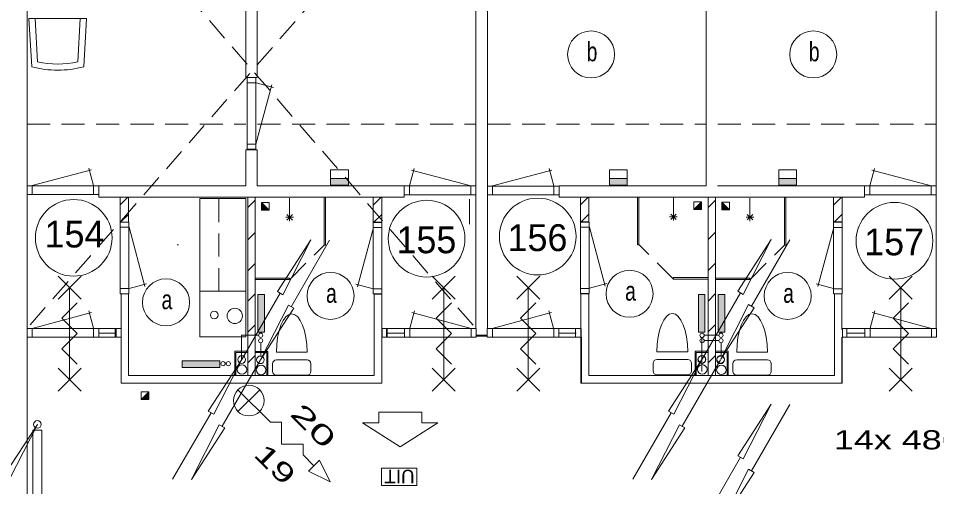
# Model space of a CAD drawing. Extents: x 295824 to 414724, y 24924 to 109024.
# Drawn here: x 301977 to 313944, y 70117 to 76222 of the extents above; entities that cross this region are included whole.
import ezdxf
from ezdxf.enums import TextEntityAlignment as Align

# ---------------------------------------------------------------- set-up
doc = ezdxf.new("R2010")
doc.units = 0
doc.header["$LTSCALE"] = 100
doc.linetypes.add('LONG_DASHED', pattern=[7.5, 6, -1.5])
doc.linetypes.add('MEDIUM_DASHED', pattern=[4.5, 3, -1.5])
doc.layers.add('16', color=7, linetype='Continuous', lineweight=13)
doc.layers.add('61', color=7, linetype='Continuous', lineweight=13)

msp = doc.modelspace()

# ---------------------------------------------------------------- hatches: boundary and pattern name
at = {"layer": '16'}
for points in [[(306277.8, 74047.1), (306046.2, 74047.1), (306046.2, 74133.6), (306277.8, 74133.6)], [(309911.3, 74047.1), (309679.8, 74047.1), (309679.8, 74133.6), (309911.3, 74133.6)], [(312117.3, 74047.1), (311885.8, 74047.1), (311885.8, 74133.6), (312117.3, 74133.6)], [(305098.5, 72622), (305183.9, 72622), (305183.9, 72129.8), (305098.5, 72129.8)], [(310838.6, 72622), (310924, 72622), (310924, 72129.8), (310838.6, 72129.8)], [(311097.8, 72622), (311183.2, 72622), (311183.2, 72129.8), (311097.8, 72129.8)], [(304110.9, 71671.9), (304110.9, 71757.4), (304603.1, 71757.4), (304603.1, 71671.9)]]:
    msp.add_hatch(color=256, dxfattribs=at).paths.add_polyline_path(points)
at = {"layer": '61'}
for points in [[(305244.4, 73722.8), (305144.4, 73822.8), (305144.4, 73722.8)], [(310781.4, 73729.4), (310881.4, 73829.4), (310881.4, 73729.4)], [(311243.8, 73724.1), (311143.8, 73824.1), (311143.8, 73724.1)], [(303578.3, 71252.8), (303678.3, 71352.8), (303678.3, 71252.8)]]:
    msp.add_hatch(color=256, dxfattribs=at).paths.add_polyline_path(points)

# ---------------------------------------------------------------- linework, layer by layer
at = {"layer": '16'}
for p, q in [((306046.2, 74133.6), (306046.2, 74247.5)), ((309679.8, 74133.6), (309679.8, 74247.5)), ((311885.8, 74133.6), (311885.8, 74247.5)), ((306031, 73329.2), (305531, 72463.2)), ((312030.4, 73336.8), (311530.4, 72470.8)), ((310887.4, 71778.5), (311387.4, 72644.5)), ((304888, 71774.7), (305388, 72640.7)), ((304886.5, 71769.9), (304886.5, 72091)), ((305106.8, 72091), (304886.5, 72091)), ((310885.9, 71619.1), (310885.9, 72055.6)), ((311106.2, 72091), (310914.5, 72091)), ((305131.1, 71769.9), (304631.1, 70903.9)), ((311127.8, 71769.9), (310627.8, 70903.9)), ((312030.4, 71187.6), (311530.4, 70321.6)), ((303987.2, 70215), (304487.2, 71081)), ((309983.9, 70215), (310483.9, 71081)), ((310887.4, 69633.3), (311387.4, 70499.3))]:
    msp.add_line(p, q, dxfattribs=at)
at = {"layer": '16', "linetype": 'LONG_DASHED'}
for p, q in [((305137.7, 71830.9), (305137.7, 71994.5)), ((310914.6, 72020.2), (311106.1, 72020.2)), ((311137.1, 71830.9), (311137.1, 71994.5))]:
    msp.add_line(p, q, dxfattribs=at)
at = {"layer": '16'}
for points in [[(306277.8, 74133.6), (306277.8, 74247.5), (306046.2, 74247.5)], [(309911.3, 74133.6), (309911.3, 74247.5), (309679.8, 74247.5)], [(312117.3, 74133.6), (312117.3, 74247.5), (311885.8, 74247.5)]]:
    msp.add_lwpolyline(points, dxfattribs=at)
for points in [[(306277.8, 74047.1), (306046.2, 74047.1), (306046.2, 74133.6), (306277.8, 74133.6)], [(309911.3, 74047.1), (309679.8, 74047.1), (309679.8, 74133.6), (309911.3, 74133.6)], [(312117.3, 74047.1), (311885.8, 74047.1), (311885.8, 74133.6), (312117.3, 74133.6)], [(305788, 73333.7), (305424, 72619.7), (305352, 72661.7)], [(311787.4, 73337.5), (311423.4, 72623.5), (311351.4, 72665.5)], [(305098.5, 72622), (305183.9, 72622), (305183.9, 72129.8), (305098.5, 72129.8)], [(310838.6, 72622), (310924, 72622), (310924, 72129.8), (310838.6, 72129.8)], [(311097.8, 72622), (311183.2, 72622), (311183.2, 72129.8), (311097.8, 72129.8)], [(305131, 71770.2), (305495, 72484.2), (305567, 72442.2)], [(311130.4, 71777.8), (311494.4, 72491.8), (311566.4, 72449.8)], [(304110.9, 71671.9), (304110.9, 71757.4), (304603.1, 71757.4), (304603.1, 71671.9)], [(304887.2, 71774), (304523.2, 71060), (304451.2, 71102)], [(310883.9, 71774), (310519.9, 71060), (310447.9, 71102)], [(311787.4, 71192.3), (311423.4, 70478.3), (311351.4, 70520.3)], [(302224.6, 70928.2), (301860.6, 70214.2), (301788.6, 70256.2)], [(302281.5, 70853.7), (302281.5, 69634.3), (302163.6, 69634.3), (302163.6, 70853.7)], [(304231.1, 70210.9), (304595.1, 70924.9), (304667.1, 70882.9)], [(310227.8, 70210.9), (310591.8, 70924.9), (310663.8, 70882.9)], [(311130.4, 69628.6), (311494.4, 70342.6), (311566.4, 70300.6)]]:
    msp.add_lwpolyline(points, close=True, dxfattribs=at)
for centre, radius in [((305134.7, 72091), 27.9), ((305134.7, 72020.2), 27.9), ((310886.7, 72088), 27.9), ((310886.7, 72020.2), 27.9), ((311134.1, 72091), 27.9), ((311134.1, 72020.2), 27.9), ((304887.2, 71773.7), 50), ((304888, 71774.4), 50), ((305131, 71770.5), 50), ((305131.1, 71770.2), 50), ((310883.9, 71773.7), 50), ((310887.4, 71778.2), 50), ((311127.8, 71770.2), 50), ((311130.4, 71778.1), 50), ((304644.9, 71720), 27.9), ((304712.7, 71720), 27.9), ((302224.6, 70927.9), 50)]:
    msp.add_circle(centre, radius, dxfattribs=at)
at = {"layer": '61'}
for p, q in [((302090.1, 72179.9), (302090.1, 78890.8)), ((307940.1, 72179.6), (307940.1, 78890.8)), ((308090.1, 72179.8), (308090.1, 78890.8)), ((313940.1, 72179.8), (313940.1, 78890.8)), ((304940.1, 76611.3), (304940.1, 75450.1)), ((305090.1, 76626), (305090.1, 75450.1)), ((302227, 75655.3), (302193.6, 76221.1)), ((302783.3, 76221.1), (302751.8, 75655.2)), ((302863.4, 76221.1), (302828.4, 75591.8)), ((305090.1, 75450.1), (304940.1, 75450.1)), ((304959, 75449.3), (305073, 75449.3)), ((304959, 75382.3), (305073, 75382.3)), ((305073.6, 74581.5), (305280.6, 75354.2)), ((305074.2, 75379.9), (305301.1, 75319.2)), ((304959, 74582.3), (305073, 74582.3)), ((304940.1, 74510.2), (305090.1, 74510.2)), ((304940.1, 74510.2), (304940.1, 74040.8)), ((305090.1, 74510.2), (305090.1, 74040.8)), ((302156.8, 74041.6), (302929.6, 74248.6)), ((302955.2, 74042.2), (302894.5, 74269)), ((307075, 74038.5), (307135.8, 74265.4)), ((307873.4, 74037.9), (307100.7, 74244.9)), ((308156.5, 74036.8), (308929.3, 74243.8)), ((308955, 74037.4), (308894.2, 74264.3)), ((313075.3, 74038.5), (313136.1, 74265.4)), ((313873.7, 74037.9), (313101, 74244.9)), ((302157.6, 73926.9), (302157.6, 74040.9)), ((302957.6, 73926.9), (302957.6, 74040.9)), ((303024.6, 73926.9), (303024.6, 74040.9)), ((304940.1, 74040.8), (303025.4, 74040.8)), ((303025.4, 74040.8), (303025.4, 73890.8)), ((305090.1, 74040.8), (307004.9, 74040.8)), ((307004.9, 74040.8), (307004.9, 73890.8)), ((307005.7, 73923.2), (307005.7, 74037.2)), ((307072.7, 73923.2), (307072.7, 74037.2)), ((307872.7, 73923.2), (307872.7, 74037.2)), ((308157.3, 73922.2), (308157.3, 74036.2)), ((308957.3, 73922.2), (308957.3, 74036.2)), ((309024.3, 73922.2), (309024.3, 74036.2)), ((311090.1, 74040.8), (313005.2, 74040.8)), ((313005.2, 74040.8), (313005.2, 73890.8)), ((313006, 73923.2), (313006, 74037.2)), ((313073, 73923.2), (313073, 74037.2)), ((313873, 73923.2), (313873, 74037.2)), ((303025.4, 73890.8), (303315.1, 73890.8)), ((307004.9, 73890.8), (303025.4, 73890.8)), ((303301.8, 73789.9), (303401.5, 73889.6)), ((303303.2, 73566.1), (303303.2, 73890.2)), ((303303.2, 73890.2), (303413.2, 73890.2)), ((303413.2, 73566.1), (303413.2, 73890.2)), ((304941.8, 72071.6), (304941.8, 73872.2)), ((304966.4, 73890.8), (304966.4, 71565.8)), ((304966.9, 73754.6), (305062.7, 73850.4)), ((305062.7, 73890.8), (305062.7, 71565.8)), ((305512, 73678.6), (305512, 73878.6)), ((305961.9, 73885.1), (305961.9, 73264.6)), ((306602.2, 73566.1), (306602.2, 73890.2)), ((306602.2, 73890.2), (306712.2, 73890.2)), ((306603.9, 73789.9), (306703.6, 73889.6)), ((306605.9, 73892.1), (306719.9, 73892.1)), ((306712.2, 73566.1), (306712.2, 73890.2)), ((307854.9, 73539.4), (307854.9, 73863.5)), ((309301.2, 73791.1), (309400.9, 73890.8)), ((309302.7, 73567.3), (309302.7, 73891.4)), ((309302.7, 73891.4), (309412.6, 73891.4)), ((309412.6, 73567.3), (309412.6, 73891.4)), ((310063.9, 73891.7), (310063.9, 73271.2)), ((310513.7, 73685.2), (310513.7, 73885.2)), ((310965.8, 73892), (310965.8, 71567)), ((310966.3, 73755.8), (311062.1, 73851.6)), ((311062.1, 73892), (311062.1, 71567)), ((311511.5, 73679.9), (311511.5, 73879.9)), ((311961.3, 73886.4), (311961.3, 73265.9)), ((312601.6, 73567.3), (312601.6, 73891.4)), ((312601.6, 73891.4), (312711.6, 73891.4)), ((312603.3, 73791.1), (312703, 73890.8)), ((312711.6, 73567.3), (312711.6, 73891.4)), ((303314.1, 73567.3), (303413.8, 73667)), ((305462, 73628.6), (305562, 73628.6)), ((305476.7, 73664), (305547.4, 73593.3)), ((305476.7, 73593.3), (305547.4, 73664)), ((305512, 73678.6), (305512, 73578.6)), ((306612.5, 73567.3), (306712.2, 73667)), ((309313.5, 73568.5), (309413.2, 73668.2)), ((310563.7, 73635.2), (310463.7, 73635.2)), ((310549.1, 73670.6), (310478.4, 73599.9)), ((310549.1, 73599.9), (310478.4, 73670.6)), ((310513.7, 73685.2), (310513.7, 73585.2)), ((311461.5, 73629.9), (311561.5, 73629.9)), ((311476.1, 73665.2), (311546.8, 73594.5)), ((311476.1, 73594.5), (311546.8, 73665.2)), ((311511.5, 73679.9), (311511.5, 73579.9)), ((312611.9, 73568.5), (312711.6, 73668.2)), ((303301.5, 73499.8), (303415.5, 73499.8)), ((303303.2, 73566.1), (303413.2, 73566.1)), ((303418.6, 73500.6), (303625.7, 72727.8)), ((306602.9, 73496.3), (306395.8, 72723.6)), ((306714.9, 73495.6), (306600.9, 73495.6)), ((306601.5, 73562.6), (306715.5, 73562.6)), ((306602.2, 73566.1), (306712.2, 73566.1)), ((306714.9, 73562.6), (306714.9, 72628.6)), ((309300.9, 73566.5), (309300.9, 72634)), ((309300.9, 73501), (309414.9, 73501)), ((309302.7, 73567.3), (309412.6, 73567.3)), ((309418, 73501.8), (309625.1, 72729.1)), ((312602.3, 73497.6), (312395.2, 72724.8)), ((312714.3, 73496.8), (312600.3, 73496.8)), ((312600.9, 73563.8), (312714.9, 73563.8)), ((312601.6, 73567.3), (312711.6, 73567.3)), ((312714.3, 73563.8), (312714.3, 72629.8)), ((304966.9, 73336.5), (305062.7, 73432.3)), ((310966.3, 73337.7), (311062.1, 73433.5)), ((304046.5, 73270), (304064.5, 73270)), ((304966.9, 72931.9), (305062.7, 73027.7)), ((310966.3, 72933.1), (311062.1, 73028.9)), ((306715.1, 72958.1), (306715.1, 72065.8)), ((302794.8, 72863), (302494.8, 72563)), ((302494.8, 72863), (302794.8, 72563)), ((305061.5, 72817.1), (305511, 72817.1)), ((305061.9, 72835.1), (305511, 72835.1)), ((305511, 72817.1), (305511, 72835.1)), ((307670.3, 72863), (307370.3, 72563)), ((307370.3, 72863), (307670.3, 72563)), ((308771.2, 72863), (308471.2, 72563)), ((308471.2, 72863), (308771.2, 72563)), ((309418.7, 72703.4), (309645.5, 72764.2)), ((310963.9, 72841.7), (310514.8, 72841.7)), ((310514.8, 72823.7), (310514.8, 72841.7)), ((310964.2, 72823.7), (310514.8, 72823.7)), ((311060.9, 72818.4), (311510.4, 72818.4)), ((311061.3, 72836.4), (311510.4, 72836.4)), ((311510.4, 72818.4), (311510.4, 72836.4)), ((313627, 72863), (313327, 72563)), ((313327, 72863), (313627, 72563)), ((302644.8, 71513), (302644.8, 72713)), ((303301.5, 72699.8), (303415.5, 72699.8)), ((303419.3, 72702.2), (303646.1, 72762.9)), ((304342, 72666.3), (304939.4, 72666.3)), ((306602.2, 72697.9), (306375.4, 72758.7)), ((306714.9, 72695.6), (306600.9, 72695.6)), ((307520.3, 71513), (307520.3, 72713)), ((308621.2, 71513), (308621.2, 72713)), ((309300.9, 72701), (309414.9, 72701)), ((312601.6, 72699.1), (312374.8, 72759.9)), ((312714.3, 72696.8), (312600.3, 72696.8)), ((313477, 71513), (313477, 72713)), ((303307.4, 72629.2), (303412.7, 72629.2)), ((303315.1, 72631.2), (303315.1, 72180.6)), ((304966.9, 72535.9), (305062.7, 72631.7)), ((306612.7, 72627.8), (306612.7, 71565.8)), ((306612.7, 72627.8), (306707.4, 72627.8)), ((309306.8, 72630.4), (309306.8, 72064.6)), ((309306.8, 72630.4), (309412.1, 72630.4)), ((310966.3, 72537.2), (311062.1, 72632.9)), ((312612.1, 72629), (312612.1, 71567)), ((312612.1, 72629), (312706.8, 72629)), ((312706.8, 72629), (312706.8, 72167)), ((302953.9, 72181), (302893.2, 72407.9)), ((307078.8, 72181.1), (307139.5, 72407.9)), ((308951.6, 72181), (308890.8, 72407.9)), ((313078.9, 72181.1), (313139.7, 72407.9)), ((302155.5, 72180.4), (302928.2, 72387.5)), ((307877.2, 72180.4), (307104.4, 72387.5)), ((308153.2, 72180.4), (308925.9, 72387.5)), ((313877.3, 72180.4), (313104.6, 72387.5)), ((302156.3, 72065.8), (302156.3, 72179.8)), ((302956.3, 72065.8), (302956.3, 72179.8)), ((303023.3, 72065.8), (303023.3, 72179.8)), ((303239.2, 72065.8), (303239.2, 72179.8)), ((303249.3, 72065.8), (303249.3, 72179.8)), ((304966.9, 72132.6), (305062.7, 72228.3)), ((306775.9, 72065.8), (306775.9, 72179.8)), ((306783.4, 72065.8), (306783.4, 72179.8)), ((307009.4, 72065.8), (307009.4, 72179.8)), ((307076.4, 72065.8), (307076.4, 72179.8)), ((307876.4, 72065.8), (307876.4, 72179.8)), ((308153.9, 72065.8), (308153.9, 72179.8)), ((308953.9, 72065.8), (308953.9, 72179.8)), ((309020.9, 72065.8), (309020.9, 72179.8)), ((309238.6, 72067), (309238.6, 72181)), ((310966.3, 72133.8), (311062.1, 72229.6)), ((312775.3, 72067), (312775.3, 72181)), ((313009.6, 72065.8), (313009.6, 72179.8)), ((313076.6, 72065.8), (313076.6, 72179.8)), ((313876.6, 72065.8), (313876.6, 72179.8)), ((302090.1, 69301.2), (302090.1, 72065.2)), ((303249.3, 72119.9), (303023.3, 72119.9)), ((304341.8, 72071.6), (304941.8, 72071.6)), ((306783.4, 72119.9), (307009.4, 72119.9)), ((307944.7, 72092.1), (308085.9, 72092.1)), ((307944.7, 72077.1), (308085.9, 72077.1)), ((309246.9, 72119.9), (309020.9, 72119.9)), ((312783.6, 72119.9), (313009.6, 72119.9)), ((304812.6, 71866.2), (304962.6, 71866.2)), ((304812.6, 71566.2), (304812.6, 71866.2)), ((304966.9, 71731.7), (305062.7, 71827.4)), ((305062.7, 71865.8), (305212.7, 71865.8)), ((305212.7, 71865.8), (305212.7, 71565.8)), ((305739.5, 71868.7), (305339.5, 71868.7)), ((310699.5, 71874.9), (310299.5, 71874.9)), ((310812, 71867.4), (310962, 71867.4)), ((310812, 71567.4), (310812, 71867.4)), ((310966.3, 71732.9), (311062.1, 71828.7)), ((311062.1, 71867), (311212.1, 71867)), ((311212.1, 71867), (311212.1, 71567)), ((311738.9, 71869.9), (311338.9, 71869.9)), ((305289.5, 71618.7), (305289.5, 71718.7)), ((305339.5, 71768.7), (305739.5, 71768.7)), ((305789.5, 71718.7), (305789.5, 71618.7)), ((310249.5, 71624.9), (310249.5, 71724.9)), ((310299.5, 71774.9), (310699.5, 71774.9)), ((310749.5, 71724.9), (310749.5, 71624.9)), ((311288.9, 71619.9), (311288.9, 71719.9)), ((311338.9, 71769.9), (311738.9, 71769.9)), ((311788.9, 71719.9), (311788.9, 71619.9)), ((302794.8, 71663), (302494.8, 71363)), ((302494.8, 71663), (302794.8, 71363)), ((305739.5, 71568.7), (305339.5, 71568.7)), ((307670.3, 71663), (307370.3, 71363)), ((307370.3, 71663), (307670.3, 71363)), ((308771.2, 71663), (308471.2, 71363)), ((308471.2, 71663), (308771.2, 71363)), ((310699.5, 71574.9), (310299.5, 71574.9)), ((311738.9, 71569.9), (311338.9, 71569.9)), ((313627, 71663), (313327, 71363)), ((313327, 71663), (313627, 71363)), ((305121.4, 71379.7), (304838.6, 71096.9))]:
    msp.add_line(p, q, dxfattribs=at)
at = {"layer": '61', "linetype": 'MEDIUM_DASHED'}
for p, q in [((302112.4, 78915.1), (307930.8, 72187.9)), ((307950.5, 78895.5), (302112.4, 72207.6)), ((302090.1, 74844.1), (304939.8, 74844.1)), ((305093, 74844.1), (307940.7, 74844.1)), ((308091.8, 74844.1), (310940.1, 74844.1)), ((311090.6, 74844.1), (313940.8, 74844.1)), ((304588.3, 72666.3), (304588.3, 73873.6)), ((305513.1, 72817.6), (305960, 73264.5)), ((310512.7, 72824.1), (310065.8, 73271)), ((311512.5, 72818.8), (311959.4, 73265.7))]:
    msp.add_line(p, q, dxfattribs=at)
at = {"layer": '61'}
for points in [[(310940.1, 79104.8), (310940.1, 74040.8), (309025.1, 74040.8), (309025.1, 73890.8), (313005.2, 73890.8)], [(302150.7, 75591.9), (302113.4, 76221.1), (302863.4, 76221.1)], [(304959, 74515.3), (305073, 74515.3), (305073, 75449.3)], [(304959, 75449.3), (304959, 74515.3), (305073, 74515.3)], [(302090.6, 73926.9), (302090.6, 74040.9), (303024.6, 74040.9)], [(303024.6, 73926.9), (302090.6, 73926.9), (302090.6, 74040.9)], [(307939.7, 73923.2), (307939.7, 74037.2), (307005.7, 74037.2)], [(307005.7, 73923.2), (307939.7, 73923.2), (307939.7, 74037.2)], [(308090.3, 73922.2), (308090.3, 74036.2), (309024.3, 74036.2)], [(309024.3, 73922.2), (308090.3, 73922.2), (308090.3, 74036.2)], [(313940, 73923.2), (313940, 74037.2), (313006, 74037.2)], [(313006, 73923.2), (313940, 73923.2), (313940, 74037.2)], [(304341.8, 72071.6), (304341.8, 73872.2), (304941.8, 73872.2)], [(305979.9, 73885.1), (305979.9, 73264.6), (305961.9, 73264.6)], [(310045.9, 73891.7), (310045.9, 73271.2), (310063.9, 73271.2)], [(311979.3, 73886.4), (311979.3, 73265.9), (311961.3, 73265.9)], [(305144.4, 73822.8), (305144.4, 73722.8), (305244.4, 73722.8)], [(310881.4, 73829.4), (310881.4, 73729.4), (310781.4, 73729.4)], [(311143.8, 73824.1), (311143.8, 73724.1), (311243.8, 73724.1)], [(303412.7, 72629.2), (303412.7, 71565.8), (306612.7, 71565.8)], [(309412.1, 72630.4), (309412.1, 71567), (312612.1, 71567)], [(302744.8, 71713), (302544.8, 71913), (302744.8, 72113), (302544.8, 72313), (302744.8, 72513)], [(307620.3, 71713), (307420.3, 71913), (307620.3, 72113), (307420.3, 72313), (307620.3, 72513)], [(308721.2, 71713), (308521.2, 71913), (308721.2, 72113), (308521.2, 72313), (308721.2, 72513)], [(313577, 71713), (313377, 71913), (313577, 72113), (313377, 72313), (313577, 72513)], [(303315.1, 72065.2), (303315.1, 71465.8), (306715.1, 71465.8), (306715.1, 72065.8)], [(309306.8, 72067), (309306.8, 71467), (312706.8, 71467), (312706.8, 72067)], [(309315.1, 72065.8), (309315.1, 71465.8), (312715.1, 71465.8), (312715.1, 72065.8)], [(304797.6, 71566.2), (304797.6, 71881.2), (304962.6, 71881.2)], [(305062.7, 71880.8), (305227.7, 71880.8), (305227.7, 71565.8)], [(310797, 71567.4), (310797, 71882.4), (310962, 71882.4)], [(311062.1, 71882), (311227.1, 71882), (311227.1, 71567)], [(303678.3, 71352.8), (303678.3, 71252.8), (303578.3, 71252.8)], [(304838.6, 71379.7), (305262.9, 70955.5), (305404.3, 70955.5), (305404.3, 70672.6), (305687.1, 70672.6), (305687.1, 70531.2), (305828.5, 70389.8)]]:
    msp.add_lwpolyline(points, dxfattribs=at)
for points in [[(305144.4, 73822.8), (305244.4, 73822.8), (305244.4, 73722.8)], [(305244.4, 73722.8), (305144.4, 73822.8), (305144.4, 73722.8)], [(310881.4, 73829.4), (310781.4, 73829.4), (310781.4, 73729.4)], [(310781.4, 73729.4), (310881.4, 73829.4), (310881.4, 73729.4)], [(311143.8, 73824.1), (311243.8, 73824.1), (311243.8, 73724.1)], [(311243.8, 73724.1), (311143.8, 73824.1), (311143.8, 73724.1)], [(303301.5, 72631.9), (303415.5, 72631.9), (303415.5, 73565.9), (303301.5, 73565.9)], [(306714.9, 73562.6), (306714.9, 72628.6), (306600.9, 72628.6), (306600.9, 73562.6)], [(309300.9, 72633.1), (309414.9, 72633.1), (309414.9, 73567.1), (309300.9, 73567.1)], [(312714.3, 73563.8), (312714.3, 72629.8), (312600.3, 72629.8), (312600.3, 73563.8)], [(302089.3, 72065.8), (302089.3, 72179.8), (303315.7, 72179.8), (303315.7, 72065.8)], [(302089.3, 72065.8), (302089.3, 72179.8), (303315.7, 72179.8), (303315.7, 72065.8)], [(306716.4, 72065.8), (306716.4, 72179.8), (307943.4, 72179.8), (307943.4, 72065.8)], [(308086.9, 72065.8), (308086.9, 72179.8), (309313.3, 72179.8), (309313.3, 72065.8)], [(308086.9, 72065.8), (308086.9, 72179.8), (309313.3, 72179.8), (309313.3, 72065.8)], [(312716.6, 72065.8), (312716.6, 72179.8), (313943.6, 72179.8), (313943.6, 72065.8)], [(303678.3, 71352.8), (303578.3, 71352.8), (303578.3, 71252.8)], [(303578.3, 71252.8), (303678.3, 71352.8), (303678.3, 71252.8)], [(306673.7, 71089.3), (307233.7, 71089.3), (307233.7, 70949.3), (307443.7, 70949.3), (306953.7, 70634.3), (306463.7, 70949.3), (306673.7, 70949.3)], [(305757.8, 70319.1), (305899.3, 70460.5), (306040.7, 70177.6)], [(307168, 70358.2), (306708.4, 70358.2), (306708.4, 70133.6), (307168, 70133.6)]]:
    msp.add_lwpolyline(points, close=True, dxfattribs=at)
for centre, radius in [((309441.3, 75751.7), 306.3), ((312336.8, 75751.7), 306.3), ((302697.7, 73360.8), 500), ((307297.3, 73350.1), 500), ((308745.1, 73377.9), 500), ((313394.5, 73322.2), 500), ((306044.7, 72603.3), 306.3), ((309942.5, 72631.2), 306.3), ((312002.7, 72603.3), 306.3), ((303900.9, 72519.7), 306.3), ((304528.9, 72355.1), 50), ((304796.8, 72342.8), 100), ((304890.2, 71643.7), 62.5), ((305140.2, 71638.2), 62.5), ((310889.6, 71644.9), 62.5), ((311139.5, 71639.4), 62.5), ((304980, 71238.3), 200)]:
    msp.add_circle(centre, radius, dxfattribs=at)
for centre, radius, start, end in [((302489.6, 76831.5), 1205.2, 257.41626, 282.56606), ((302489.6, 76831.5), 1285.2, 254.70731, 285.28507), ((305339.5, 71718.7), 50, 90, 180), ((305739.5, 71718.7), 50, 0, 90), ((310299.5, 71724.9), 50, 90, 180), ((310699.5, 71724.9), 50, 0, 90), ((311338.9, 71720), 50, 90, 180), ((311738.9, 71720), 50, 0, 90), ((305339.5, 71618.7), 50, 180, 270), ((305739.5, 71618.7), 50, 270, 0), ((310299.5, 71624.9), 50, 180, 270), ((310699.5, 71624.9), 50, 270, 0), ((311338.9, 71620), 50, 180, 270), ((311738.9, 71620), 50, 270, 0)]:
    msp.add_arc(centre, radius, start, end, dxfattribs=at)
for centre in [(305539.5, 71868.7), (310499.5, 71874.9), (311538.9, 71870)]:
    msp.add_ellipse(centre, major_axis=(0, 500), ratio=0.4, start_param=4.712389, end_param=7.8539816, dxfattribs=at)

# ---------------------------------------------------------------- texts
at = {"layer": '16', "width": 1.4}
msp.add_text('14x 486-600-10', height=250, dxfattribs=at).set_placement((312605.1, 70602.4))
at = {"layer": '61', "width": 0.75}
for s, p in [('b', (309383.3, 75662.5)), ('b', (312278.8, 75662.5)), ('a', (305986.7, 72514.1)), ('a', (309884.5, 72542)), ('a', (311944.7, 72514.1)), ('a', (303842.9, 72430.6))]:
    msp.add_text(s, height=250, dxfattribs=at).set_placement(p)
at = {"layer": '61'}
for s, p in [('154', (302708, 73235.3)), ('155', (307294.4, 73160.2)), ('156', (308742.1, 73188.1)), ('157', (313390.2, 73132.3))]:
    msp.add_text(s, height=350, dxfattribs=at).set_placement(p, align=Align.CENTER)
for s, height, rotation, width, p in [('20', 250, 315, 1.75, (305502.6, 71053.1)), ('19', 250, 315, 1.55, (305030.3, 70524.6)), ('UIT', 175, 180, 1.05, (307141.3, 70336.8))]:
    msp.add_text(s, height=height, rotation=rotation, dxfattribs=dict(at, width=width)).set_placement(p)

doc.saveas('drawing.dxf')
